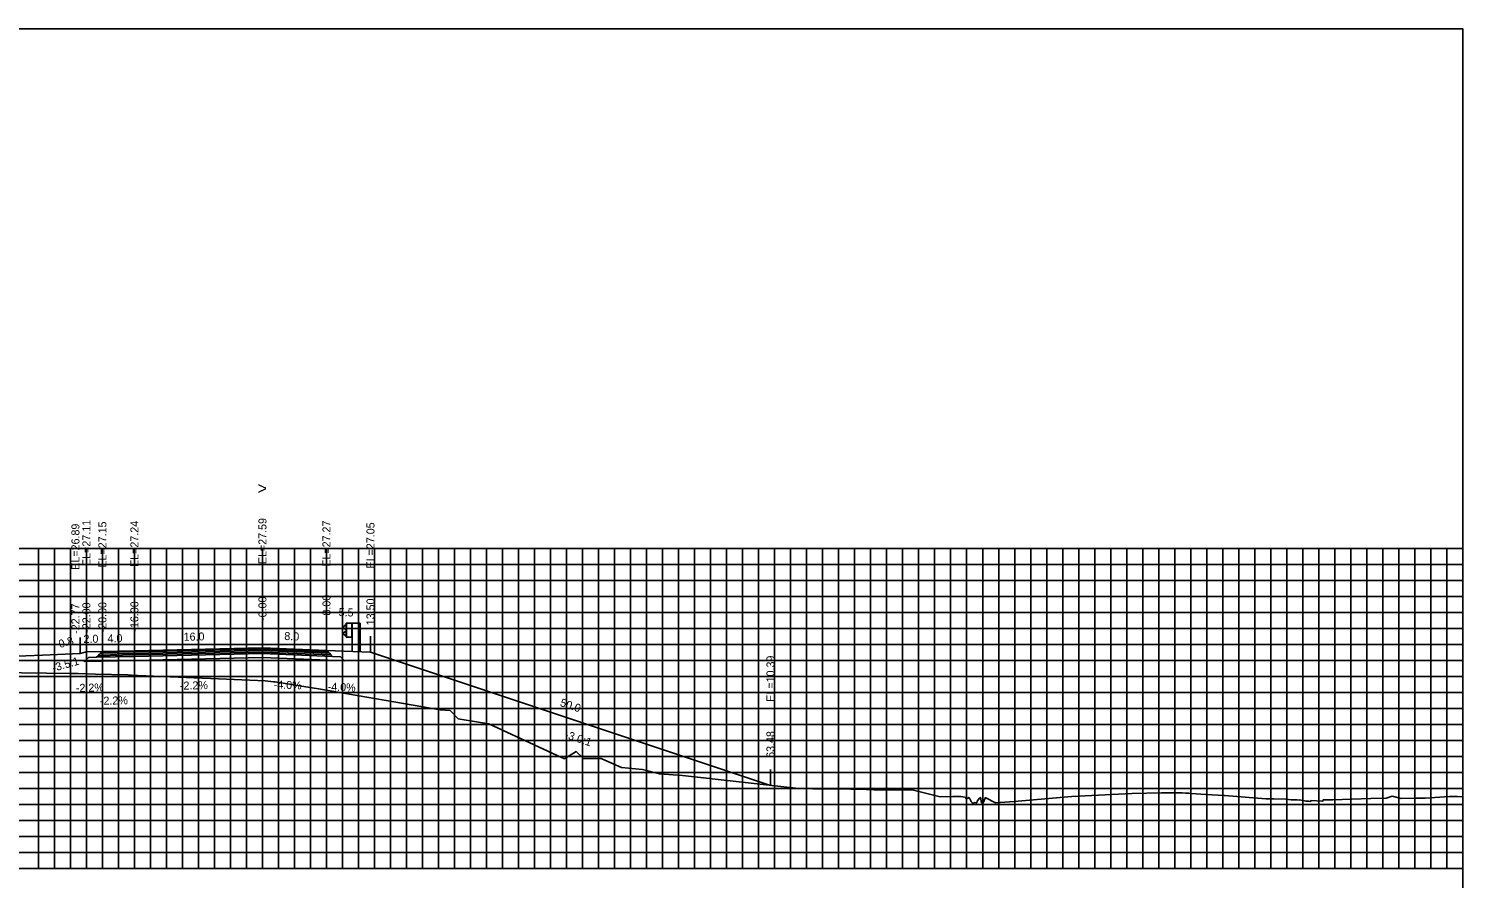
# Model space of a CAD drawing. Extents: x 1797652 to 1804145, y 245981 to 250269.
# Drawn here: x 1803621.8 to 1803801.1, y 250163.2 to 250269.4 of the extents above; entities that cross this region are included whole.
import ezdxf

# ---------------------------------------------------------------- set-up
doc = ezdxf.new("R2010")
doc.units = 0
for name, color, linetype in [('3', 7, 'Continuous'), ('4', 7, 'Continuous'), ('60', 7, 'Continuous'), ('BASE', 7, 'Continuous'), ('CL-CNST', 7, 'Continuous'), ('Level 1', 7, 'Continuous'), ('Level 62', 7, 'Continuous'), ('LOWER BINDER', 7, 'Continuous'), ('M-ROADS', 7, 'Continuous'), ('UPPER BINDER', 7, 'Continuous'), ('WEARING', 7, 'Continuous')]:
    doc.layers.add(name, color=color, linetype=linetype)

msp = doc.modelspace()

# ---------------------------------------------------------------- linework, layer by layer
for p, q in [((1803651, 250192.02), (1803651, 250194.02)), ((1803628.23, 250191.32), (1803628.23, 250193.32)), ((1803629, 250191.54), (1803629, 250193.54)), ((1803631, 250191.58), (1803631, 250193.58)), ((1803635, 250191.67), (1803635, 250193.67)), ((1803659, 250191.7), (1803659, 250193.7)), ((1803664.5, 250191.48), (1803664.5, 250193.48)), ((1803714.48, 250174.82), (1803714.48, 250176.82))]:
    msp.add_line(p, q)
msp.add_lwpolyline([(1803501, 250079.43), (1803801, 250079.43), (1803801, 250269.43), (1803501, 250269.43)], close=True)
at = {"layer": '60'}
for p, q in [((1803801, 250164.43), (1803801, 250204.43)), ((1803801.06, 250204.43), (1803801, 250204.43)), ((1803801.06, 250194.43), (1803801, 250194.43)), ((1803801.06, 250184.43), (1803801, 250184.43)), ((1803801.06, 250174.43), (1803801, 250174.43)), ((1803501, 250164.43), (1803801, 250164.43)), ((1803631, 250164.37), (1803631, 250164.43)), ((1803641, 250164.37), (1803641, 250164.43)), ((1803651, 250164.37), (1803651, 250164.43)), ((1803661, 250164.37), (1803661, 250164.43)), ((1803671, 250164.37), (1803671, 250164.43)), ((1803681, 250164.37), (1803681, 250164.43)), ((1803691, 250164.37), (1803691, 250164.43)), ((1803701, 250164.37), (1803701, 250164.43)), ((1803711, 250164.37), (1803711, 250164.43)), ((1803721, 250164.37), (1803721, 250164.43)), ((1803731, 250164.37), (1803731, 250164.43)), ((1803741, 250164.37), (1803741, 250164.43)), ((1803751, 250164.37), (1803751, 250164.43)), ((1803761, 250164.37), (1803761, 250164.43)), ((1803771, 250164.37), (1803771, 250164.43)), ((1803781, 250164.37), (1803781, 250164.43)), ((1803791, 250164.37), (1803791, 250164.43)), ((1803801, 250164.37), (1803801, 250164.43)), ((1803801.06, 250164.43), (1803801, 250164.43))]:
    msp.add_line(p, q, dxfattribs=at)
at = {"layer": 'BASE'}
msp.add_lwpolyline([(1803629.27, 250190.82), (1803630.27, 250190.84), (1803635, 250190.95), (1803651, 250191.3), (1803659.75, 250190.95), (1803660.75, 250190.91), (1803661.27, 250190.39), (1803651, 250190.8), (1803635, 250190.45), (1803628.75, 250190.31)], close=True, dxfattribs=at)
at = {"layer": 'CL-CNST'}
for points in [[(1803628.23, 250191.32), (1803629, 250191.54), (1803631, 250191.58), (1803635, 250191.67), (1803651, 250192.02), (1803659, 250191.7), (1803664.5, 250191.48), (1803714.48, 250174.82)], [(1803616.19, 250190.83), (1803623.52, 250191.12), (1803628.23, 250191.32)]]:
    msp.add_lwpolyline(points, dxfattribs=at)
at = {"layer": 'Level 1'}
for p, q in [((1803661.46, 250194.95), (1803661.1, 250194.65)), ((1803661.1, 250194.58), (1803661.46, 250194.29)), ((1803661.46, 250194.15), (1803661.1, 250193.85)), ((1803661.1, 250193.78), (1803661.46, 250193.5)), ((1803661.46, 250195.1), (1803661.46, 250193.35)), ((1803663.21, 250195.1), (1803661.46, 250195.1)), ((1803661.51, 250195.1), (1803661.51, 250193.35)), ((1803662.16, 250195.1), (1803662.16, 250193.35)), ((1803662.21, 250195.1), (1803662.21, 250191.57)), ((1803663.21, 250195.1), (1803663.21, 250191.53)), ((1803662.21, 250193.35), (1803661.46, 250193.35))]:
    msp.add_line(p, q, dxfattribs=at)
for centre in [(1803661.13, 250194.61), (1803661.13, 250193.82)]:
    msp.add_arc(centre, 0.05, 135, 226.6208, dxfattribs=at)
at = {"layer": 'Level 62'}
for p, q in [((1803501, 250204.43), (1803801, 250204.43)), ((1803623, 250164.43), (1803623, 250204.43)), ((1803625, 250164.43), (1803625, 250204.43)), ((1803627, 250164.43), (1803627, 250204.43)), ((1803629, 250164.43), (1803629, 250204.43)), ((1803631, 250164.43), (1803631, 250204.43)), ((1803633, 250164.43), (1803633, 250204.43)), ((1803635, 250164.43), (1803635, 250204.43)), ((1803637, 250164.43), (1803637, 250204.43)), ((1803639, 250164.43), (1803639, 250204.43)), ((1803641, 250164.43), (1803641, 250204.43)), ((1803643, 250164.43), (1803643, 250204.43)), ((1803645, 250164.43), (1803645, 250204.43)), ((1803647, 250164.43), (1803647, 250204.43)), ((1803649, 250164.43), (1803649, 250204.43)), ((1803651, 250164.43), (1803651, 250204.43)), ((1803653, 250164.43), (1803653, 250204.43)), ((1803655, 250164.43), (1803655, 250204.43)), ((1803657, 250164.43), (1803657, 250204.43)), ((1803659, 250164.43), (1803659, 250204.43)), ((1803661, 250164.43), (1803661, 250204.43)), ((1803663, 250164.43), (1803663, 250204.43)), ((1803665, 250164.43), (1803665, 250204.43)), ((1803667, 250164.43), (1803667, 250204.43)), ((1803669, 250164.43), (1803669, 250204.43)), ((1803671, 250164.43), (1803671, 250204.43)), ((1803673, 250164.43), (1803673, 250204.43)), ((1803675, 250164.43), (1803675, 250204.43)), ((1803677, 250164.43), (1803677, 250204.43)), ((1803679, 250164.43), (1803679, 250204.43)), ((1803681, 250164.43), (1803681, 250204.43)), ((1803683, 250164.43), (1803683, 250204.43)), ((1803685, 250164.43), (1803685, 250204.43)), ((1803687, 250164.43), (1803687, 250204.43)), ((1803689, 250164.43), (1803689, 250204.43)), ((1803691, 250164.43), (1803691, 250204.43)), ((1803693, 250164.43), (1803693, 250204.43)), ((1803695, 250164.43), (1803695, 250204.43)), ((1803697, 250164.43), (1803697, 250204.43)), ((1803699, 250164.43), (1803699, 250204.43)), ((1803701, 250164.43), (1803701, 250204.43)), ((1803703, 250164.43), (1803703, 250204.43)), ((1803705, 250164.43), (1803705, 250204.43)), ((1803707, 250164.43), (1803707, 250204.43)), ((1803709, 250164.43), (1803709, 250204.43)), ((1803711, 250164.43), (1803711, 250204.43)), ((1803713, 250164.43), (1803713, 250204.43)), ((1803715, 250164.43), (1803715, 250204.43)), ((1803717, 250164.43), (1803717, 250204.43)), ((1803719, 250164.43), (1803719, 250204.43)), ((1803721, 250164.43), (1803721, 250204.43)), ((1803723, 250164.43), (1803723, 250204.43)), ((1803725, 250164.43), (1803725, 250204.43)), ((1803727, 250164.43), (1803727, 250204.43)), ((1803729, 250164.43), (1803729, 250204.43)), ((1803731, 250164.43), (1803731, 250204.43)), ((1803733, 250164.43), (1803733, 250204.43)), ((1803735, 250164.43), (1803735, 250204.43)), ((1803737, 250164.43), (1803737, 250204.43)), ((1803739, 250164.43), (1803739, 250204.43)), ((1803741, 250164.43), (1803741, 250204.43)), ((1803743, 250164.43), (1803743, 250204.43)), ((1803745, 250164.43), (1803745, 250204.43)), ((1803747, 250164.43), (1803747, 250204.43)), ((1803749, 250164.43), (1803749, 250204.43)), ((1803751, 250164.43), (1803751, 250204.43)), ((1803753, 250164.43), (1803753, 250204.43)), ((1803755, 250164.43), (1803755, 250204.43)), ((1803757, 250164.43), (1803757, 250204.43)), ((1803759, 250164.43), (1803759, 250204.43)), ((1803761, 250164.43), (1803761, 250204.43)), ((1803763, 250164.43), (1803763, 250204.43)), ((1803765, 250164.43), (1803765, 250204.43)), ((1803767, 250164.43), (1803767, 250204.43)), ((1803769, 250164.43), (1803769, 250204.43)), ((1803771, 250164.43), (1803771, 250204.43)), ((1803773, 250164.43), (1803773, 250204.43)), ((1803775, 250164.43), (1803775, 250204.43)), ((1803777, 250164.43), (1803777, 250204.43)), ((1803779, 250164.43), (1803779, 250204.43)), ((1803781, 250164.43), (1803781, 250204.43)), ((1803783, 250164.43), (1803783, 250204.43)), ((1803785, 250164.43), (1803785, 250204.43)), ((1803787, 250164.43), (1803787, 250204.43)), ((1803789, 250164.43), (1803789, 250204.43)), ((1803791, 250164.43), (1803791, 250204.43)), ((1803793, 250164.43), (1803793, 250204.43)), ((1803795, 250164.43), (1803795, 250204.43)), ((1803797, 250164.43), (1803797, 250204.43)), ((1803799, 250164.43), (1803799, 250204.43)), ((1803801, 250164.43), (1803801, 250204.43)), ((1803501, 250202.43), (1803801, 250202.43)), ((1803501, 250200.43), (1803801, 250200.43)), ((1803501, 250198.43), (1803801, 250198.43)), ((1803501, 250196.43), (1803801, 250196.43)), ((1803501, 250194.43), (1803801, 250194.43)), ((1803501, 250192.43), (1803801, 250192.43)), ((1803501, 250190.43), (1803801, 250190.43)), ((1803501, 250188.43), (1803801, 250188.43)), ((1803501, 250186.43), (1803801, 250186.43)), ((1803501, 250184.43), (1803801, 250184.43)), ((1803501, 250182.43), (1803801, 250182.43)), ((1803501, 250180.43), (1803801, 250180.43)), ((1803501, 250178.43), (1803801, 250178.43)), ((1803501, 250176.43), (1803801, 250176.43)), ((1803501, 250174.43), (1803801, 250174.43)), ((1803501, 250172.43), (1803801, 250172.43)), ((1803501, 250170.43), (1803801, 250170.43)), ((1803501, 250168.43), (1803801, 250168.43)), ((1803501, 250166.43), (1803801, 250166.43)), ((1803501, 250164.43), (1803801, 250164.43))]:
    msp.add_line(p, q, dxfattribs=at)
at = {"layer": 'LOWER BINDER'}
for points in [[(1803635, 250191.14), (1803651, 250191.49), (1803659.55, 250191.15), (1803659.75, 250190.95), (1803651, 250191.3), (1803635, 250190.95), (1803630.27, 250190.84), (1803630.46, 250191.04)], [(1803635, 250191.33), (1803651, 250191.68), (1803659.36, 250191.35), (1803659.55, 250191.15), (1803651, 250191.49), (1803635, 250191.14), (1803630.46, 250191.04), (1803630.65, 250191.23)]]:
    msp.add_lwpolyline(points, close=True, dxfattribs=at)
at = {"layer": 'M-ROADS'}
msp.add_lwpolyline([(1803617.77, 250188.93), (1803624, 250188.85), (1803626.89, 250188.81), (1803627.83, 250188.8), (1803627.97, 250188.8), (1803629.08, 250188.77), (1803630.13, 250188.74), (1803634.18, 250188.63), (1803634.63, 250188.61), (1803635.43, 250188.58), (1803646.52, 250188.1), (1803651.33, 250187.88), (1803652.39, 250187.77), (1803652.58, 250187.76), (1803653.2, 250187.64), (1803653.6, 250187.59), (1803658.25, 250186.85), (1803673.21, 250184.26), (1803674.44, 250184.19), (1803675.46, 250183.15), (1803678, 250182.74), (1803679.28, 250182.53), (1803688.38, 250178.3), (1803688.76, 250178.15), (1803688.78, 250178.18), (1803690.19, 250179.06), (1803691.13, 250178.18), (1803693.34, 250178.18), (1803693.79, 250177.98), (1803695.88, 250177.08), (1803698.49, 250176.8), (1803700.6, 250176.26), (1803703.47, 250176.08), (1803718.01, 250174.42), (1803719.77, 250174.38), (1803721.2, 250174.38), (1803722.55, 250174.38), (1803726.46, 250174.3), (1803727.46, 250174.28), (1803729.67, 250174.28), (1803732.01, 250174.28), (1803732.19, 250174.26), (1803735.69, 250173.41), (1803737.27, 250173.42), (1803738.29, 250173.42), (1803738.76, 250173.36), (1803738.85, 250173.29), (1803739.04, 250173.15), (1803739.27, 250173.33), (1803739.4, 250173.15), (1803739.56, 250172.8), (1803739.68, 250172.68), (1803739.73, 250172.51), (1803739.96, 250172.69), (1803740.17, 250172.64), (1803740.2, 250172.64), (1803740.27, 250172.64), (1803740.32, 250172.85), (1803740.6, 250173.24), (1803740.71, 250173.34), (1803740.85, 250172.65), (1803740.92, 250172.58), (1803741.02, 250172.49), (1803741.03, 250172.74), (1803741.03, 250172.81), (1803741.04, 250172.62), (1803741.06, 250172.63), (1803741.34, 250173.3), (1803741.38, 250173.27), (1803742.61, 250172.65), (1803744.93, 250172.82), (1803752.16, 250173.45), (1803759.62, 250173.83), (1803763.36, 250173.88), (1803763.57, 250173.88), (1803763.78, 250173.88), (1803765.95, 250173.88), (1803766.38, 250173.85), (1803766.48, 250173.85), (1803766.75, 250173.84), (1803767.06, 250173.82), (1803768.88, 250173.7), (1803771.19, 250173.55), (1803771.22, 250173.56), (1803776.38, 250173.14), (1803777.38, 250173.15), (1803778.89, 250173.12), (1803779.53, 250173.04), (1803779.98, 250173.03), (1803780.28, 250173.02), (1803780.54, 250173), (1803780.59, 250173.01), (1803781.23, 250172.88), (1803781.38, 250172.86), (1803781.76, 250172.84), (1803781.96, 250172.82), (1803781.99, 250172.83), (1803782.02, 250172.95), (1803783.47, 250172.84), (1803783.59, 250173.04), (1803784.74, 250173.03), (1803789.51, 250173.21), (1803791.44, 250173.24), (1803792.19, 250173.47), (1803793.28, 250173.17), (1803795.17, 250173.24), (1803795.18, 250173.24), (1803796.31, 250173.22), (1803799.32, 250173.44), (1803800.35, 250173.46), (1803801, 250173.41)], dxfattribs=at)
at = {"layer": 'UPPER BINDER'}
msp.add_lwpolyline([(1803659.36, 250191.35), (1803659.16, 250191.54), (1803651, 250191.87), (1803635, 250191.52), (1803630.85, 250191.43), (1803630.65, 250191.23), (1803635, 250191.33), (1803651, 250191.68)], close=True, dxfattribs=at)
at = {"layer": 'WEARING'}
msp.add_lwpolyline([(1803659.16, 250191.54), (1803659, 250191.7), (1803651, 250192.02), (1803635, 250191.67), (1803631, 250191.58), (1803630.85, 250191.43), (1803635, 250191.52), (1803651, 250191.87)], close=True, dxfattribs=at)

# ---------------------------------------------------------------- texts
for s, rotation, p in [('-3.5:1', 15.8703, (1803624.88, 250189.02)), ('-3.0:1', 341.5652, (1803688.7, 250180.78))]:
    msp.add_text(s, height=1, rotation=rotation).set_placement(p)
at = {"layer": '3'}
for s, p in [('EL=27.59', (1803651.5, 250202.49)), ('EL=26.89', (1803628.13, 250201.79)), ('EL=27.11', (1803629.5, 250202.26)), ('EL=27.15', (1803631.5, 250202.05)), ('EL=27.24', (1803635.5, 250202.14)), ('EL=27.27', (1803659.5, 250202.17)), ('EL=27.05', (1803665, 250201.95)), ('-22.77', (1803628.13, 250193.77)), ('-22.00', (1803629.5, 250193.91)), ('-20.00', (1803631.5, 250193.96)), ('-16.00', (1803635.5, 250194.05)), ('-0.00', (1803651.5, 250195.39)), ('8.00', (1803659.5, 250196.06)), ('13.50', (1803665, 250194.85)), ('EL=10.39', (1803714.98, 250185.29)), ('63.48', (1803714.98, 250178.27))]:
    msp.add_text(s, height=1, rotation=90, dxfattribs=at).set_placement(p)
at = {"layer": '4'}
for s, rotation, p in [('5.5', 357.7094, (1803660.51, 250196.01)), ('16.0', 1.2603, (1803641.16, 250192.9)), ('8.0', 357.7094, (1803653.72, 250193.01)), ('0.8', 15.8703, (1803625.69, 250191.99)), ('2.0', 1.2603, (1803628.65, 250192.63)), ('4.0', 1.2603, (1803631.65, 250192.7)), ('-2.2%', 1.2603, (1803627.7, 250186.51)), ('-2.2%', 1.2603, (1803640.7, 250186.79)), ('-4.0%', 357.7094, (1803652.39, 250186.96)), ('-4.0%', 357.7094, (1803659.14, 250186.69)), ('-2.2%', 1.2603, (1803630.7, 250184.9)), ('50.0', 341.5652, (1803688.11, 250184.77))]:
    msp.add_text(s, height=1, rotation=rotation, dxfattribs=at).set_placement(p)
at = {"layer": '60'}
msp.add_text('>', height=1.5, dxfattribs=at).set_placement((1803650.39, 250211.23))

doc.saveas('drawing.dxf')
